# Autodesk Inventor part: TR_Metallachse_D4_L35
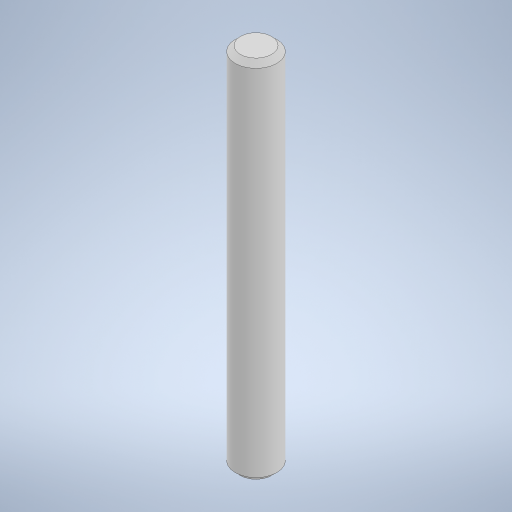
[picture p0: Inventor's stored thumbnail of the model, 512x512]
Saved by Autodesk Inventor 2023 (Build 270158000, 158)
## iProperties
Created: 2023-11
Part Number: TR_Metallachse_D4_L35
Material: Generisch
Document SubType Name: Modeling
Designer: Greiner
Density: 1 g/cm^3
Appearance: Vorgabe
Author: Greiner
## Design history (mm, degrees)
sketch "Skizze1"
  geometry: C1 r 2 at (0, 0); 1 further point
  constraints: 1 centre point, 1 coincident
  dimensions: "d0" = 4 diameter of C1 (= AchsDurchmesser)
extrude "Extrusion1" new body sketch "Skizze1" distance "d1" = 35; taper "d2" = 0 deg
chamfer "Fase1" distance "d3" = 0.5 (= AchsFase); stored, may be unused: second distance "d4" = 2, angle "d5" = 45 deg
node "Volumenkörper1"
other parameters: "Radius" = 2.075 [user parameter], "Fasen" = 0.5 [user parameter], "Dicke" = 0.8 [user parameter], "Breitloch" = 2 [user parameter], "Langloch" = 32 [user parameter], "AchteckUmkreis" = 6 [user parameter], "DAchsAufnahme" = 4.1 [user parameter], "AchsDurchmesser" = 4 [user parameter; used in 1 equation term], "AchsFase" = 0.5 [user parameter; used in 1 equation term]
